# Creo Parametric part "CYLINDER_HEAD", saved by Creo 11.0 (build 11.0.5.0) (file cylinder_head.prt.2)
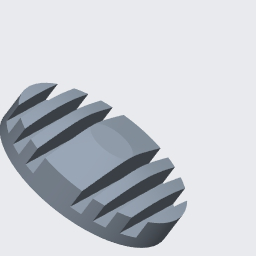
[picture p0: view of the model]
Materials in the file: 10038_S235JR

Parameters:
  MATERIAL = "10038_S235JR"
  PTC_MATERIAL_NAME = "10038_S235JR"
  PTC_MASTER_MATERIAL = "10038_S235JR"
  SELECT_EN_NAME = "S235JR"
  SELECT_DIN_NAME = "RSt37-2"
  SELECT_MATERIAL_NUMBER = "1.0038"
  SELECT_ASTM_NAME = "A 283 M Grade 2"
  MATERIAL_GROUP = "ME_ST_Baustahl"
  STANDARD_EN_DELIVERYSPEC = "DIN EN 10025-2"
  STANDARD_DIN_DELIVERYSPEC = "DIN EN 10025-2"

Other parameters: GEWICHT

Created from: STARTTEIL.PRT

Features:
  1. datum plane "RIGHT"
  2. datum plane "TOP"
  3. datum plane "FRONT"
  4. coordinate system
  5. datum axis
  6. datum axis
  7. datum axis
  8. revolve "Revolve 1"
  9. pattern "Pattern 1"
  10. extruded cut "Extrude 1"
  11. extruded cut "Extrude 1 [2]"
  12. extruded cut "Extrude 1 [3]"
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
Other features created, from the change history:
  extrusion "Extrude 1"
  mirror "Mirror 1"
  pattern "Pattern 1 (2)"
  extruded cut "Extrude 1 (2) [1]"
  extruded cut "Extrude 1 (2) [2]"
  extruded cut "Extrude 1 (2) [3]"
  mirror "Mirror 2"
  pattern "Pattern 1 (3)"
  extruded cut "Extrude 1 (3) [1]"
  extruded cut "Extrude 1 (3) [2]"
  extruded cut "Extrude 1 (3) [3]"
  mirror "Mirror 3"
  pattern "Pattern 1 (4)"
  extruded cut "Extrude 1 (4) [1]"
  extruded cut "Extrude 1 (4) [2]"
  extruded cut "Extrude 1 (4) [3]"

Other named items: A_Y, A_X, A_Z, CS0

Surfaces: 20 plane, 2 cylinder, 2 cone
